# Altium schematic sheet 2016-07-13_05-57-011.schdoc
size 313 x 144 mm; SheetNumber: 1; SheetTotal: 1
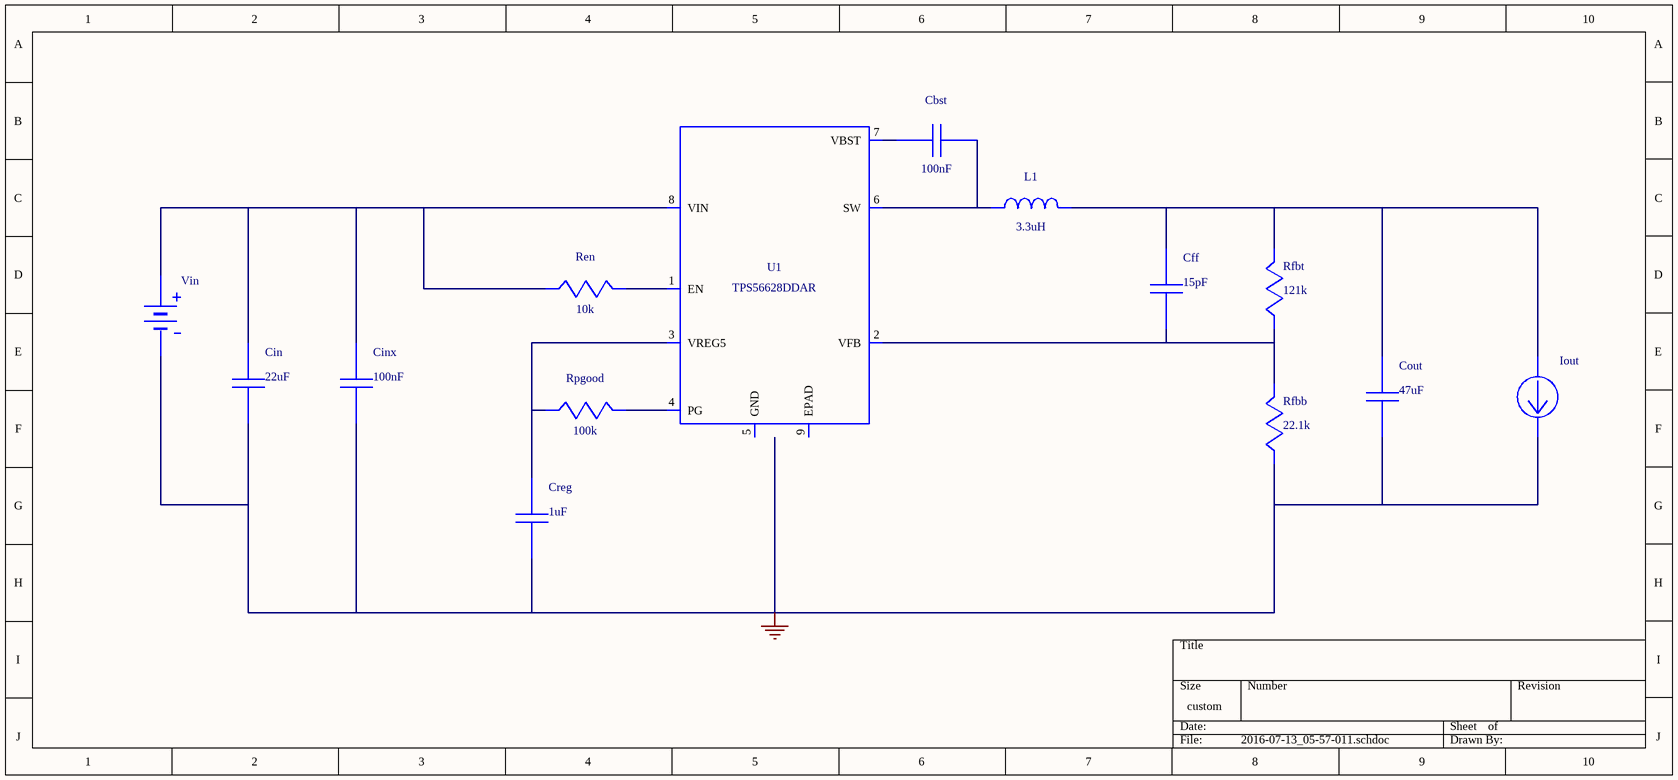
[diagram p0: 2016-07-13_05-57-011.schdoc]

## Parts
Cbst  value 100nF  (hidden comment: 06033C104KAT2A)
Cff  value 15pF  (hidden comment: C0603C150M8GACTU)
Cin  value 22uF  (hidden comment: GRM32ER61E226KE15L)
Cinx  value 100nF  (hidden comment: 06033C104KAT2A)
Cout  value 47uF  (hidden comment: GRM31CR61A476KE15L)
Creg  value 1uF  (hidden comment: GRM188R61A105KA61D)
Iout  WB_CURRENT_LOAD  (value not drawn)
L1  value 3.3uH  (hidden comment: SRN6045-3R3Y)
Ren  value 10k  (hidden comment: CRCW040210K0FKED)
Rfbb  value 22.1k  (hidden comment: CRCW040222K1FKED)
Rfbt  value 121k  (hidden comment: CRCW0402121KFKED)
Rpgood  value 100k  (hidden comment: CRCW0402100KFKED)
U1  TPS56528DDAR  (value not drawn)
Vin  WB_BATTERY  (value not drawn)

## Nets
0: Cin.2 Cinx.2 Cout.2 Creg.2 Iout.2(-) Rfbb.2 Vin.2(-)
NetCbst_1: Cbst.1 U1.7(VBST)
NetCbst_2: Cbst.2 L1.1 U1.6(SW)
NetCff_1: Cff.1 Cout.1 Iout.1(+) L1.2 Rfbt.1
NetCff_2: Cff.2 Rfbb.1 Rfbt.2 U1.2(VFB)
NetCin_1: Cin.1 Cinx.1 Ren.2 U1.8(VIN) Vin.1(+)
NetCreg_1: Creg.1 Rpgood.2 U1.3(VREG5)
NetRen_1: Ren.1 U1.1(EN)
NetRpgood_1: Rpgood.1 U1.4(PG)

Not connected (* = marked no-connect by the designer): U1 5(GND) 9(EPAD)

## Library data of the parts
Cbst Cinx = 06033C104KAT2A: Manufacturer Name: AVX
Cff = C0603C150M8GACTU: Manufacturer Name: Kemet
Cin = GRM32ER61E226KE15L: GRM32ER61E226KE1; Manufacturer Name: MuRata
Cout = GRM31CR61A476KE15L: GRM31CR61A476KE1; Manufacturer Name: MuRata
Creg = GRM188R61A105KA61D: GRM188R61A105KA6; Manufacturer Name: MuRata
L1 = SRN6045-3R3Y: Manufacturer Name: Bourns
Ren = CRCW040210K0FKED: Manufacturer Name: Vishay-Dale
Rfbb = CRCW040222K1FKED: Manufacturer Name: Vishay-Dale
Rfbt = CRCW0402121KFKED: Manufacturer Name: Vishay-Dale
Rpgood = CRCW0402100KFKED: Manufacturer Name: Vishay-Dale
U1 = TPS56528DDAR: TPS56628DDAR; Manufacturer Name: Texas Instruments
